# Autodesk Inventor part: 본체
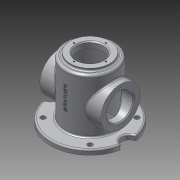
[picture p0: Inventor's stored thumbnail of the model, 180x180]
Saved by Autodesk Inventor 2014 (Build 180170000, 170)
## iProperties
Created: 2018-04
Part Number: 본체
Material: 알루미늄 6061
Document SubType Name: Modeling
Designer: OA62
Density: 2.71 g/cm^3
Appearance: 알루미늄 - 평지
Mass: 1147.09 g
Surface Area: 1195.3 cm^2
Volume: 423.281 cm^3
Author: OA62
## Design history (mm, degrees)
sketch "스케치1"
  geometry: L1 (0, 0)-(80, 0); L2 (80, 0)-(80, 133); L3 (80, 133)-(0, 133); L4 (0, 133)-(0, 0); L5 (50, 0)-(50, 8); L6 (50, 8)-(80, 8); L7 (80, 18)-(50, 18); L8 (50, 18)-(50, 128); L9 (50, 128)-(40, 128); L10 (40, 128)-(40, 133); L11 (27, 120)-(27, 133); L12 (27, 120)-(0, 120); 1 further point
  constraints: 24 end point, 6 point on line, 5 perpendicular, 4 parallel, 1 horizontal, 1 midpoint
  dimensions: "d0" = 80 distance of L3.end L2.end; "d1" = 133 distance of L1.end L2.end; "d2" = 50 distance between parallel lines of L4 L5; "d3" = 8 distance between parallel lines of L1 L6; "d4" = 10 distance between parallel lines of L7 L6; "d5" = 50 distance between parallel lines of L4 L8; "d6" = 40 distance between parallel lines of L4 L10; "d7" = 5 distance between parallel lines of L3 L9; "d10" = 27 distance between parallel lines of L4 L11; "d30" = 13 distance between parallel lines of L3 L12
revolve "회전1" sketch "스케치1" stored, may be unused: angle "d12" = 90 deg
sketch "스케치2"
  geometry: C1 r 50 at (0, 0) reference; C2 r 15 at (-80, 0); C3 r 15 at (80, 0); A1 r 80 centre (0, 0) between (-80, 0) and (80, 0) reference
  constraints: 2 centre point, 2 horizontal alignment, 2 point on circle
  dimensions: "d13" = 30 diameter of C2; "d14" = 30 diameter of C3
extrude "돌출1" cut sketch "스케치2" stored distance "d15" = 10; taper "d16" = 0 deg
sketch "스케치3"
  geometry: L1 (47.73, -47.73)-(-47.73, 47.73); L2 (-47.73, -47.73)-(47.73, 47.73); L3 (0, 0)-(0, 67.5); C1 r 50 at (0, 0) reference; A1 r 67.5 centre (0, 0) between (-47.73, 47.73) and (47.73, 47.73); 4 further points
  constraints: 6 end point, 5 coincident, 5 point on circle, 2 midpoint, 1 centre point, 1 vertical
  dimensions: "d17" = 135 diameter of A1; "d18" = 45 deg angle of L3 L1; "d19" = 90 deg angle of L2 L1
hole "구멍1" sketch "스케치3" at (-47.73, 47.73), (47.73, 47.73), (-47.73, -47.73), (47.73, -47.73) diameter "d20" = 10; stored, may be unused: countersink angle "d24" = 90 deg, drill point angle "d26" = 118 deg; dims "d21" = 6, "d22" = 4, "d23" = 2, "d25" = 8
sketch "스케치4"
  geometry: C1 r 40 at (68, 0); 1 further point
  constraints: 1 centre point, 1 horizontal alignment
  dimensions: "d27" = 80 diameter of C1; "d31" = 68 distance of point (0, 0) C1.centre
extrude "돌출2" join sketch "스케치4" stored distance "d32" = 124; taper "d33" = 0 deg
sketch "스케치5"
  geometry: C1 r 40 at (0, 0) reference; C2 r 27 at (0, 0); 1 further point
  constraints: 1 centre point, 1 coincident
  dimensions: "d34" = 54 diameter of C2
extrude "돌출3" cut sketch "스케치5" distance "d35" = 124; taper "d36" = 0 deg
sketch "스케치6"
  geometry: C1 r 50 at (0, 0) reference; C2 r 45 at (0, 0)
  constraints: 1 centre point, 1 coincident
  dimensions: "d37" = 90 diameter of C2
extrude "돌출4" cut sketch "스케치6" distance "d38" = 120; taper "d39" = 0 deg
sketch "스케치7"
  geometry: C1 r 27 at (0, 0) reference; 1 further point
  constraints: 1 horizontal alignment
  dimensions: "d40" = 32.5 distance of point (32.5, 0) C1.centre
hole "구멍2" sketch "스케치7" at (32.5, 0) diameter "d41" = 3.242; stored, may be unused: countersink angle "d45" = 90 deg, drill point angle "d47" = 118 deg; dims "d42" = 8, "d43" = 4, "d44" = 2, "d46" = 10
sketch "스케치8"
  geometry: C1 r 27 at (0, 0) reference; 2 further points
  constraints: 1 vertical alignment
  dimensions: "d51" = 32.5 distance of C1.centre point (0, 32.5)
hole "구멍3" sketch "스케치8" at (0, 32.5) diameter "d52" = 3.242; stored, may be unused: countersink angle "d56" = 90 deg, drill point angle "d58" = 118 deg; dims "d53" = 8, "d54" = 4, "d55" = 2, "d57" = 10
node "작업 평면1"
sketch "스케치9"
  geometry: L1 (-78.594, 8)-(78.594, 8) reference; 2 further points
  constraints: 1 vertical alignment, 1 other
  dimensions: "d63" = 70 distance from line of L1 point (0, 78)
feature "엠보싱1" sketch "스케치9" dims "d0" = 80, "d1" = 133, "d2" = 50, "d3" = 8, "d4" = 10, "d5" = 50, "d6" = 40, "d7" = 5, "d10" = 27, "d30" = 13, "d64" = 0.5, "d65" = 0
fillet "모깎기1" dims "d66" = 5
fillet "모깎기2" dims "d67" = 3
fillet "모깎기3" dims "d68" = 3
chamfer "모따기1" distance "d70" = 2; stored, may be unused: second distance "d71" = 2, angle "d72" = 45 deg
node "솔리드1"
pattern_circular "원형 패턴1" dims angle "d49" = 360 deg
pattern_circular "원형 패턴2" dims angle "d60" = 360 deg
mirror "대칭1"
